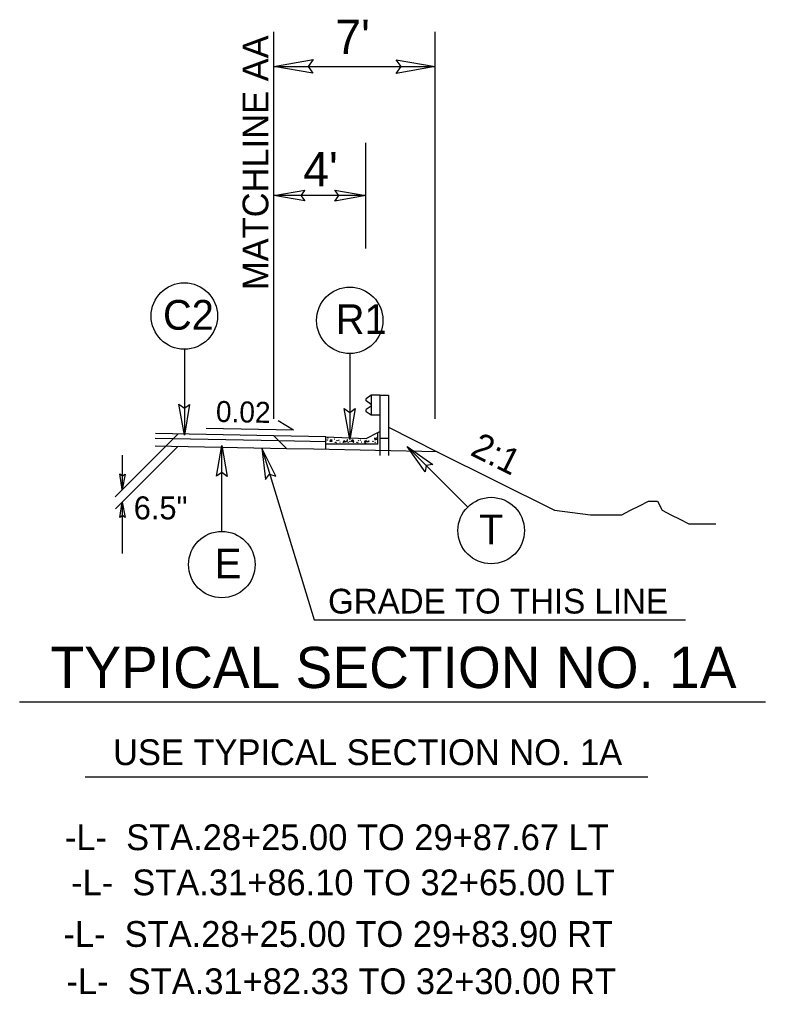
# Model space of a CAD drawing. Extents: x 1818040 to 1825768, y 638918 to 648046.
# Drawn here: x 1819129.23 to 1819161.64, y 645878.57 to 645920.9 of the extents above; entities that cross this region are included whole.
import ezdxf

# ---------------------------------------------------------------- set-up
doc = ezdxf.new("R2010")
doc.units = 0
for name, color, linetype in [('Old_Level_1', 7, 'Continuous'), ('Prop Dimension', 7, 'Continuous'), ('Prop Dimension Text', 7, 'Continuous'), ('Typical Curb CELL', 7, 'Continuous'), ('Typical Guardrail CELL', 7, 'Continuous'), ('Typical ID Circle CELL', 7, 'Continuous'), ('Typical Pavement Slope CELL', 7, 'Continuous'), ('Typical Pavement Slope Information CELL', 7, 'Continuous'), ('Typical Slope Point Local CELL', 7, 'Continuous'), ('Typical Terminator CELL', 7, 'Continuous'), ('Typical Text General CELL', 7, 'Continuous'), ('Typical Text Grade Point CELL', 7, 'Continuous'), ('Typical Text ID Circle CELL', 7, 'Continuous'), ('Typical Text Label CELL', 7, 'Continuous')]:
    doc.layers.add(name, color=color, linetype=linetype)

msp = doc.modelspace()

# ---------------------------------------------------------------- linework, layer by layer
at = {"layer": 'Old_Level_1'}
for p, q in [((1819144.803, 645902.971), (1819144.886, 645903.012)), ((1819136.115, 645902.904), (1819133.394, 645900.183)), ((1819140.5, 645902.608), (1819135.131, 645902.715)), ((1819140.288, 645902.82), (1819140.84, 645902.267)), ((1819142.538, 645902.567), (1819140.5, 645902.608)), ((1819136.115, 645902.362), (1819133.408, 645899.655)), ((1819140.84, 645902.267), (1819135.125, 645902.382)), ((1819139.76, 645902.289), (1819142.039, 645894.834)), ((1819142.022, 645902.244), (1819140.84, 645902.267)), ((1819147.384, 645902.137), (1819142.022, 645902.244)), ((1819142.538, 645902.234), (1819142.538, 645902.463)), ((1819133.7, 645901.98), (1819133.7, 645900.497)), ((1819133.7, 645899.947), (1819133.7, 645897.715)), ((1819142.039, 645894.834), (1819158.164, 645894.834))]:
    msp.add_line(p, q, dxfattribs=at)
at = {"layer": 'Prop Dimension'}
for p, q in [((1819140.288, 645903.567), (1819140.288, 645920.365)), ((1819147.288, 645903.567), (1819147.288, 645920.365)), ((1819140.288, 645918.865), (1819147.288, 645918.865)), ((1819144.271, 645910.965), (1819144.271, 645915.548)), ((1819144.271, 645913.256), (1819140.288, 645913.256))]:
    msp.add_line(p, q, dxfattribs=at)
at = {"layer": 'Typical Curb CELL'}
for p, q in [((1819144.288, 645902.713), (1819144.803, 645902.971)), ((1819144.803, 645902.463), (1819144.803, 645902.971)), ((1819142.538, 645902.775), (1819142.538, 645902.775)), ((1819142.538, 645902.463), (1819142.538, 645902.767)), ((1819142.546, 645902.775), (1819144.288, 645902.713)), ((1819142.716, 645902.577), (1819142.781, 645902.667)), ((1819142.807, 645902.581), (1819142.716, 645902.577)), ((1819142.781, 645902.667), (1819142.807, 645902.581)), ((1819143.29, 645902.538), (1819143.337, 645902.624)), ((1819143.414, 645902.568), (1819143.29, 645902.538)), ((1819143.337, 645902.624), (1819143.414, 645902.568)), ((1819143.653, 645902.577), (1819143.717, 645902.667)), ((1819143.743, 645902.581), (1819143.653, 645902.577)), ((1819143.717, 645902.667), (1819143.743, 645902.581)), ((1819144.227, 645902.538), (1819144.274, 645902.624)), ((1819144.351, 645902.568), (1819144.227, 645902.538)), ((1819144.274, 645902.624), (1819144.351, 645902.568)), ((1819144.66, 645902.721), (1819144.673, 645902.653)), ((1819144.776, 645902.687), (1819144.66, 645902.721)), ((1819144.673, 645902.653), (1819144.776, 645902.687)), ((1819144.803, 645902.463), (1819142.538, 645902.463))]:
    msp.add_line(p, q, dxfattribs=at)
for centre in [(1819142.605, 645902.642), (1819142.634, 645902.736), (1819142.909, 645902.68), (1819142.954, 645902.546), (1819142.996, 645902.521), (1819143.02, 645902.616), (1819143.077, 645902.614), (1819143.115, 645902.637), (1819143.15, 645902.55), (1819143.295, 645902.58), (1819143.45, 645902.568), (1819143.462, 645902.605), (1819143.47, 645902.65), (1819143.513, 645902.543), (1819143.585, 645902.577), (1819143.655, 645902.584), (1819143.745, 645902.546), (1819143.891, 645902.546), (1819143.933, 645902.521), (1819143.957, 645902.616), (1819144.051, 645902.637), (1819144.087, 645902.55), (1819144.232, 645902.58), (1819144.386, 645902.568), (1819144.399, 645902.605), (1819144.592, 645902.584), (1819144.682, 645902.546), (1819144.755, 645902.751), (1819144.254, 645902.503)]:
    msp.add_circle(centre, 0.00602, dxfattribs=at)
msp.add_arc((1819142.546, 645902.767), 0.00781, 87.952, 180, dxfattribs=at)
at = {"layer": 'Typical Guardrail CELL'}
for p, q in [((1819144.514, 645904.587), (1819144.296, 645904.435)), ((1819144.514, 645904.187), (1819144.296, 645904.339)), ((1819144.886, 645904.587), (1819144.514, 645904.587)), ((1819144.514, 645904.587), (1819144.514, 645903.717)), ((1819144.886, 645904.587), (1819144.886, 645902.723)), ((1819144.886, 645904.587), (1819145.259, 645904.587)), ((1819145.259, 645904.587), (1819145.259, 645902.723)), ((1819144.514, 645904.117), (1819144.296, 645903.965)), ((1819144.514, 645903.717), (1819144.296, 645903.869)), ((1819144.514, 645904.152), (1819144.514, 645904.187)), ((1819144.514, 645904.152), (1819144.514, 645904.117)), ((1819144.886, 645903.717), (1819144.514, 645903.717)), ((1819144.886, 645902.723), (1819145.259, 645902.723)), ((1819144.886, 645902.723), (1819144.886, 645901.966)), ((1819145.259, 645902.723), (1819145.259, 645901.966))]:
    msp.add_line(p, q, dxfattribs=at)
for centre, start, end in [((1819144.33, 645904.387), 125.003, 235.0112), ((1819144.33, 645903.917), 125.0059, 235.0366)]:
    msp.add_arc(centre, 0.0582, start, end, dxfattribs=at)
at = {"layer": 'Typical ID Circle CELL'}
for p, q in [((1819136.394, 645906.584), (1819136.394, 645902.856)), ((1819143.579, 645906.397), (1819143.579, 645902.669)), ((1819138.022, 645898.676), (1819138.022, 645902.404)), ((1819148.705, 645899.732), (1819146.068, 645902.368))]:
    msp.add_line(p, q, dxfattribs=at)
for centre in [(1819136.394, 645908.026), (1819143.579, 645907.839), (1819149.724, 645898.712), (1819138.022, 645897.234)]:
    msp.add_circle(centre, 1.443, dxfattribs=at)
at = {"layer": 'Typical Pavement Slope CELL'}
for p, q in [((1819140.288, 645902.82), (1819135.135, 645902.923)), ((1819142.538, 645902.775), (1819140.288, 645902.82))]:
    msp.add_line(p, q, dxfattribs=at)
at = {"layer": 'Typical Pavement Slope Information CELL'}
for q in [(1819140.466, 645903.477), (1819137.344, 645903.145)]:
    msp.add_line((1819141.142, 645903.069), q, dxfattribs=at)
at = {"layer": 'Typical Slope Point Local CELL'}
for p, q in [((1819145.259, 645903.199), (1819147.384, 645902.137)), ((1819147.384, 645902.137), (1819152.475, 645899.591))]:
    msp.add_line(p, q, dxfattribs=at)
msp.add_lwpolyline([(1819152.475, 645899.591), (1819154.031, 645899.397), (1819154.42, 645899.397), (1819155.004, 645899.397), (1819155.393, 645899.397), (1819155.782, 645899.591), (1819156.171, 645899.786), (1819156.56, 645899.982), (1819156.949, 645899.982), (1819157.144, 645899.591), (1819157.533, 645899.397), (1819157.922, 645899.202), (1819158.311, 645899.008), (1819158.7, 645899.008), (1819159.089, 645899.008), (1819159.478, 645899.008)], dxfattribs=at)
at = {"layer": 'Typical Terminator CELL'}
for points in [[(1819141.975, 645918.575), (1819140.288, 645918.865), (1819141.984, 645919.165), (1819141.769, 645918.865)], [(1819145.6, 645919.156), (1819147.288, 645918.865), (1819145.591, 645918.565), (1819145.806, 645918.865)], [(1819141.623, 645913.026), (1819140.288, 645913.256), (1819141.631, 645913.494), (1819141.46, 645913.256)], [(1819142.936, 645913.486), (1819144.271, 645913.256), (1819142.928, 645913.019), (1819143.099, 645913.256)], [(1819136.624, 645904.191), (1819136.394, 645902.856), (1819136.157, 645904.199), (1819136.394, 645904.028)], [(1819143.809, 645904.005), (1819143.579, 645902.669), (1819143.341, 645904.012), (1819143.579, 645903.841)], [(1819137.792, 645901.069), (1819138.022, 645902.404), (1819138.26, 645901.061), (1819138.022, 645901.232)], [(1819140.365, 645901.075), (1819139.758, 645902.287), (1819139.92, 645900.933), (1819140.097, 645901.165)], [(1819146.85, 645901.261), (1819146.068, 645902.368), (1819147.186, 645901.586), (1819146.897, 645901.539)], [(1819133.82, 645901.164), (1819133.7, 645900.497), (1819133.587, 645901.17), (1819133.705, 645901.083)], [(1819133.587, 645899.279), (1819133.7, 645899.947), (1819133.821, 645899.276), (1819133.702, 645899.361)]]:
    msp.add_lwpolyline(points, close=True, dxfattribs=at)
at = {"layer": 'Typical Text Label CELL'}
for p, q in [((1819129.233, 645891.274), (1819161.64, 645891.274)), ((1819132.087, 645888.02), (1819156.528, 645888.02))]:
    msp.add_line(p, q, dxfattribs=at)

# ---------------------------------------------------------------- texts
at = {"layer": 'Prop Dimension Text'}
for s, height, p in [("7'", 1.5, (1819142.957, 645919.403)), ("4'", 1.5, (1819141.564, 645913.652)), ('6.5"', 1, (1819134.196, 645899.197))]:
    msp.add_text(s, height=height, dxfattribs=at).set_placement(p)
at = {"layer": 'Typical Pavement Slope Information CELL'}
msp.add_text('0.02 ', height=0.9107, rotation=358.8543, dxfattribs=at).set_placement((1819137.76, 645903.431))
at = {"layer": 'Typical Text General CELL'}
msp.add_text('GRADE TO THIS LINE', height=1.0742, dxfattribs=at).set_placement((1819142.637, 645895.109))
at = {"layer": 'Typical Text Grade Point CELL'}
for s, p in [('-L-  STA.28+25.00 TO 29+87.67 LT', (1819131.207, 645884.834)), ('-L-  STA.31+86.10 TO 32+65.00 LT', (1819131.475, 645882.875)), ('-L-  STA.28+25.00 TO 29+83.90 RT', (1819131.141, 645880.635)), ('-L-  STA.31+82.33 TO 32+30.00 RT', (1819131.275, 645878.582))]:
    msp.add_text(s, height=1.11896, dxfattribs=at).set_placement(p)
at = {"layer": 'Typical Text ID Circle CELL'}
for s, height, p in [('C2', 1.2912, (1819135.468, 645907.432)), ('R1', 1.2912, (1819142.974, 645907.245)), ('T', 1.291, (1819149.196, 645898.117)), ('E', 1.291, (1819137.719, 645896.64))]:
    msp.add_text(s, height=height, dxfattribs=at).set_placement(p)
at = {"layer": 'Typical Text Label CELL'}
for s, height, rotation, p in [('MATCHLINE AA', 1.11896, 90, (1819140.044, 645909.156)), ('2:1', 1.119, 333.4349, (1819148.764, 645902.015))]:
    msp.add_text(s, height=height, rotation=rotation, dxfattribs=at).set_placement(p)
for s, height, p in [('TYPICAL SECTION NO. 1A', 1.79034, (1819130.583, 645891.873)), ('USE TYPICAL SECTION NO. 1A', 1.11896, (1819133.298, 645888.527))]:
    msp.add_text(s, height=height, dxfattribs=at).set_placement(p)

doc.saveas('drawing.dxf')
